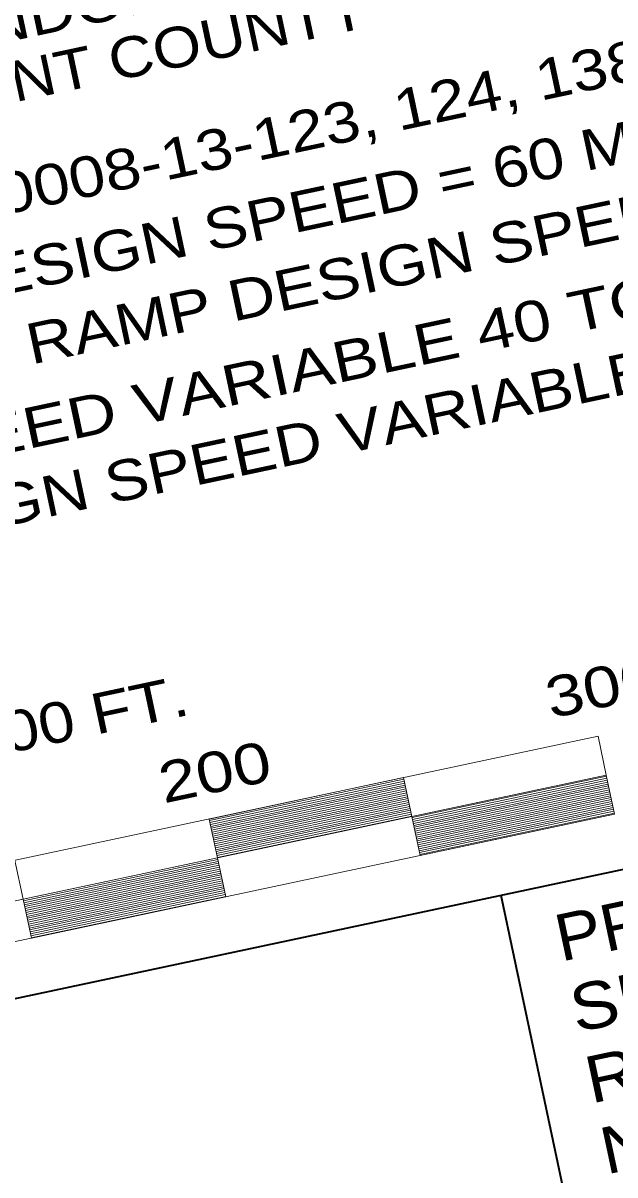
# Model space of a CAD drawing. Extents: x 2357218 to 2371708, y 6973728 to 6980157.
# Drawn here: x 2370806.3 to 2370955.3, y 6976807.8 to 6977097.4 of the extents above; entities that cross this region are included whole.
import ezdxf
from ezdxf.enums import TextEntityAlignment as Align

# ---------------------------------------------------------------- set-up
doc = ezdxf.new("R2010")
doc.units = 0
doc.header["$LTSCALE"] = 2
doc.layers.add('61', color=7, linetype='Continuous')
doc.layers.add('62', color=7, linetype='Continuous', lineweight=13)
doc.layers.add('63', color=7, linetype='Continuous', lineweight=13)

msp = doc.modelspace()

# ---------------------------------------------------------------- linework, layer by layer
at = {"layer": '62', "lineweight": 35}
for p, q in [((2371176.22, 6976931.098), (2370539.396, 6976795.736)), ((2370972.547, 6976661.874), (2370926.598, 6976878.04))]:
    msp.add_line(p, q, dxfattribs=at)
at = {"layer": '62'}
for p, q in [((2370559.68, 6976834.897), (2370950.993, 6976918.073)), ((2370950.993, 6976918.073), (2370953.073, 6976908.29)), ((2370561.761, 6976825.114), (2370953.073, 6976908.29)), ((2370853.246, 6976896.896), (2370902.159, 6976907.293)), ((2370853.351, 6976896.406), (2370902.264, 6976906.803)), ((2370902.078, 6976907.676), (2370904.157, 6976897.894)), ((2370904.214, 6976897.632), (2370953.127, 6976908.028)), ((2370904.318, 6976897.143), (2370953.231, 6976907.54)), ((2370904.421, 6976896.653), (2370953.336, 6976907.051)), ((2370904.524, 6976896.164), (2370953.439, 6976906.56)), ((2370953.073, 6976908.29), (2370955.152, 6976898.507)), ((2370853.455, 6976895.917), (2370902.367, 6976906.314)), ((2370853.557, 6976895.429), (2370902.472, 6976905.825)), ((2370853.661, 6976894.94), (2370902.575, 6976905.335)), ((2370853.765, 6976894.45), (2370902.679, 6976904.847)), ((2370853.87, 6976893.961), (2370902.784, 6976904.358)), ((2370853.973, 6976893.472), (2370902.887, 6976903.868)), ((2370904.628, 6976895.676), (2370953.543, 6976906.072)), ((2370904.732, 6976895.186), (2370953.647, 6976905.583)), ((2370904.836, 6976894.697), (2370953.751, 6976905.095)), ((2370904.94, 6976894.208), (2370953.856, 6976904.606)), ((2370905.045, 6976893.719), (2370953.959, 6976904.116)), ((2370905.149, 6976893.23), (2370954.063, 6976903.628)), ((2370854.077, 6976892.983), (2370902.991, 6976903.379)), ((2370854.182, 6976892.494), (2370903.095, 6976902.889)), ((2370854.285, 6976892.004), (2370903.2, 6976902.4)), ((2370854.39, 6976891.515), (2370903.304, 6976901.912)), ((2370854.493, 6976891.026), (2370903.407, 6976901.423)), ((2370854.598, 6976890.537), (2370903.51, 6976900.935)), ((2370905.253, 6976892.741), (2370954.168, 6976903.138)), ((2370905.357, 6976892.252), (2370954.272, 6976902.649)), ((2370905.459, 6976891.762), (2370954.376, 6976902.16)), ((2370905.564, 6976891.273), (2370954.479, 6976901.67)), ((2370905.668, 6976890.783), (2370954.583, 6976901.181)), ((2370905.772, 6976890.294), (2370954.687, 6976900.691)), ((2370854.701, 6976890.048), (2370903.615, 6976900.445)), ((2370854.805, 6976889.559), (2370903.72, 6976899.956)), ((2370854.91, 6976889.07), (2370903.823, 6976899.468)), ((2370855.013, 6976888.581), (2370903.927, 6976898.978)), ((2370855.118, 6976888.092), (2370904.031, 6976898.489)), ((2370855.222, 6976887.603), (2370904.134, 6976897.999)), ((2370904.157, 6976897.894), (2370906.237, 6976888.11)), ((2370905.876, 6976889.805), (2370954.791, 6976900.202)), ((2370905.98, 6976889.316), (2370954.896, 6976899.713)), ((2370906.085, 6976888.827), (2370954.999, 6976899.224)), ((2370906.189, 6976888.338), (2370955.104, 6976898.735)), ((2370853.165, 6976897.279), (2370855.245, 6976887.496)), ((2370804.251, 6976886.882), (2370806.329, 6976877.099)), ((2370806.41, 6976876.716), (2370855.324, 6976887.113)), ((2370806.515, 6976876.227), (2370855.429, 6976886.624)), ((2370855.245, 6976887.496), (2370857.323, 6976877.714)), ((2370806.618, 6976875.738), (2370855.533, 6976886.135)), ((2370806.722, 6976875.249), (2370855.638, 6976885.646)), ((2370806.827, 6976874.76), (2370855.741, 6976885.157)), ((2370806.93, 6976874.271), (2370855.844, 6976884.669)), ((2370807.034, 6976873.782), (2370855.949, 6976884.18)), ((2370807.138, 6976873.293), (2370856.052, 6976883.691)), ((2370807.242, 6976872.804), (2370856.157, 6976883.202)), ((2370807.347, 6976872.315), (2370856.261, 6976882.712)), ((2370807.45, 6976871.825), (2370856.364, 6976882.223)), ((2370807.555, 6976871.336), (2370856.469, 6976881.734)), ((2370807.658, 6976870.846), (2370856.572, 6976881.244)), ((2370807.763, 6976870.356), (2370856.678, 6976880.754)), ((2370807.866, 6976869.868), (2370856.781, 6976880.265)), ((2370807.97, 6976869.379), (2370856.884, 6976879.776)), ((2370808.074, 6976868.89), (2370856.988, 6976879.288)), ((2370808.178, 6976868.401), (2370857.092, 6976878.798)), ((2370808.283, 6976867.912), (2370857.197, 6976878.309)), ((2370808.387, 6976867.424), (2370857.3, 6976877.82)), ((2370806.329, 6976877.099), (2370808.409, 6976867.316))]:
    msp.add_line(p, q, dxfattribs=at)
for points in [[(2370855.245, 6976887.496), (2370904.157, 6976897.894), (2370902.078, 6976907.676), (2370853.165, 6976897.279)], [(2370906.237, 6976888.11), (2370955.152, 6976898.507), (2370953.073, 6976908.29), (2370904.157, 6976897.894)], [(2370757.416, 6976866.702), (2370806.329, 6976877.099), (2370804.251, 6976886.882), (2370755.336, 6976876.485)], [(2370808.409, 6976867.316), (2370857.323, 6976877.714), (2370855.245, 6976887.496), (2370806.329, 6976877.099)]]:
    msp.add_lwpolyline(points, close=True, dxfattribs=at)
at = {"layer": '63'}
for p, q in [((2370559.68, 6976834.897), (2370950.993, 6976918.073)), ((2370950.993, 6976918.073), (2370953.073, 6976908.29)), ((2370561.761, 6976825.114), (2370953.073, 6976908.29)), ((2370853.246, 6976896.896), (2370902.159, 6976907.293)), ((2370853.351, 6976896.406), (2370902.264, 6976906.803)), ((2370902.078, 6976907.676), (2370904.157, 6976897.894)), ((2370904.214, 6976897.632), (2370953.127, 6976908.028)), ((2370904.318, 6976897.143), (2370953.231, 6976907.54)), ((2370904.421, 6976896.653), (2370953.336, 6976907.051)), ((2370904.524, 6976896.164), (2370953.439, 6976906.56)), ((2370953.073, 6976908.29), (2370955.152, 6976898.507)), ((2370853.455, 6976895.917), (2370902.367, 6976906.314)), ((2370853.557, 6976895.429), (2370902.472, 6976905.825)), ((2370853.661, 6976894.94), (2370902.575, 6976905.335)), ((2370853.765, 6976894.45), (2370902.679, 6976904.847)), ((2370853.87, 6976893.961), (2370902.784, 6976904.358)), ((2370853.973, 6976893.472), (2370902.887, 6976903.868)), ((2370904.628, 6976895.676), (2370953.543, 6976906.072)), ((2370904.732, 6976895.186), (2370953.647, 6976905.583)), ((2370904.836, 6976894.697), (2370953.751, 6976905.095)), ((2370904.94, 6976894.208), (2370953.856, 6976904.606)), ((2370905.045, 6976893.719), (2370953.959, 6976904.116)), ((2370905.149, 6976893.23), (2370954.063, 6976903.628)), ((2370854.077, 6976892.983), (2370902.991, 6976903.379)), ((2370854.182, 6976892.494), (2370903.095, 6976902.889)), ((2370854.285, 6976892.004), (2370903.2, 6976902.4)), ((2370854.39, 6976891.515), (2370903.304, 6976901.912)), ((2370854.493, 6976891.026), (2370903.407, 6976901.423)), ((2370854.598, 6976890.537), (2370903.51, 6976900.935)), ((2370905.253, 6976892.741), (2370954.168, 6976903.138)), ((2370905.357, 6976892.252), (2370954.272, 6976902.649)), ((2370905.459, 6976891.762), (2370954.376, 6976902.16)), ((2370905.564, 6976891.273), (2370954.479, 6976901.67)), ((2370905.668, 6976890.783), (2370954.583, 6976901.181)), ((2370905.772, 6976890.294), (2370954.687, 6976900.691)), ((2370563.839, 6976815.332), (2370955.152, 6976898.507)), ((2370854.701, 6976890.048), (2370903.615, 6976900.445)), ((2370854.805, 6976889.559), (2370903.72, 6976899.956)), ((2370854.91, 6976889.07), (2370903.823, 6976899.468)), ((2370855.013, 6976888.581), (2370903.927, 6976898.978)), ((2370855.118, 6976888.092), (2370904.031, 6976898.489)), ((2370855.222, 6976887.603), (2370904.134, 6976897.999)), ((2370904.157, 6976897.894), (2370906.237, 6976888.11)), ((2370905.876, 6976889.805), (2370954.791, 6976900.202)), ((2370905.98, 6976889.316), (2370954.896, 6976899.713)), ((2370906.085, 6976888.827), (2370954.999, 6976899.224)), ((2370906.189, 6976888.338), (2370955.104, 6976898.735)), ((2370853.165, 6976897.279), (2370855.245, 6976887.496)), ((2370804.251, 6976886.882), (2370806.329, 6976877.099)), ((2370806.41, 6976876.716), (2370855.324, 6976887.113)), ((2370806.515, 6976876.227), (2370855.429, 6976886.624)), ((2370855.245, 6976887.496), (2370857.323, 6976877.714)), ((2370806.618, 6976875.738), (2370855.533, 6976886.135)), ((2370806.722, 6976875.249), (2370855.638, 6976885.646)), ((2370806.827, 6976874.76), (2370855.741, 6976885.157)), ((2370806.93, 6976874.271), (2370855.844, 6976884.669)), ((2370807.034, 6976873.782), (2370855.949, 6976884.18)), ((2370807.138, 6976873.293), (2370856.052, 6976883.691)), ((2370807.242, 6976872.804), (2370856.157, 6976883.202)), ((2370807.347, 6976872.315), (2370856.261, 6976882.712)), ((2370807.45, 6976871.825), (2370856.364, 6976882.223)), ((2370807.555, 6976871.336), (2370856.469, 6976881.734)), ((2370807.658, 6976870.846), (2370856.572, 6976881.244)), ((2370807.763, 6976870.356), (2370856.678, 6976880.754)), ((2370807.866, 6976869.868), (2370856.781, 6976880.265)), ((2370807.97, 6976869.379), (2370856.884, 6976879.776)), ((2370808.074, 6976868.89), (2370856.988, 6976879.288)), ((2370808.178, 6976868.401), (2370857.092, 6976878.798)), ((2370808.283, 6976867.912), (2370857.197, 6976878.309)), ((2370808.387, 6976867.424), (2370857.3, 6976877.82)), ((2370806.329, 6976877.099), (2370808.409, 6976867.316))]:
    msp.add_line(p, q, dxfattribs=at)
for points in [[(2370855.245, 6976887.496), (2370904.157, 6976897.894), (2370902.078, 6976907.676), (2370853.165, 6976897.279)], [(2370906.237, 6976888.11), (2370955.152, 6976898.507), (2370953.073, 6976908.29), (2370904.157, 6976897.894)], [(2370757.416, 6976866.702), (2370806.329, 6976877.099), (2370804.251, 6976886.882), (2370755.336, 6976876.485)], [(2370808.409, 6976867.316), (2370857.323, 6976877.714), (2370855.245, 6976887.496), (2370806.329, 6976877.099)]]:
    msp.add_lwpolyline(points, close=True, dxfattribs=at)

# ---------------------------------------------------------------- texts
at = {"layer": '61'}
for s, width, p in [('LIMITS: IH820 NORTH INTERCHANGE AT SH121', 1.15, (2370806.917, 6977109.14)), ('SOUTH TO RANDOL MILL ROAD', 1.2, (2370810.078, 6977094.271)), ('IN TARRANT COUNTY', 1.15, (2370813.239, 6977079.404))]:
    msp.add_text(s, height=10.2, rotation=12, dxfattribs=dict(at, width=width)).set_placement(p, align=Align.CENTER)
at = {"layer": '62'}
for s, height, width, p in [('CONTROL NO.  0008-13-123, 124, 138', 10.2, 1.2, (2370681.072, 6977023.559)), ('PRELIMINARY PLAN', 11.74, 1.1, (2370941.659, 6976861.386)), ('SUBMITTAL FOR', 11.74, 1.15, (2370945.453, 6976843.542)), ('NOT FOR CONSTRUCTION.', 11.74, 1.15, (2370953.039, 6976807.854)), ('REVIEW ONLY', 11.74, 1.15, (2370949.246, 6976825.698))]:
    msp.add_text(s, height=height, rotation=12, dxfattribs=dict(at, width=width)).set_placement(p)
for s, width, p in [('MAIN LANES DESIGN SPEED = 60 MPH', 1.2, (2370834.598, 6977036.084)), ('DIRECT CONNECTOR & RAMP DESIGN SPEED = 50 MPH', 1.2, (2370838.46, 6977017.911)), ('RAMP DESIGN SPEED VARIABLE 40 TO 50 MPH', 1.25, (2370842.737, 6976997.784)), ('FRONTAGE ROAD DESIGN SPEED VARIABLE 35 TO 40 MPH', 1.2, (2370847.295, 6976980.56)), ('300', 1.25, (2370952.994, 6976925.492)), ('SCALE:  1 INCH = 100 FT.', 1.2, (2370752.789, 6976903.182)), ('200', 1.25, (2370855.618, 6976904.13))]:
    msp.add_text(s, height=10.2, rotation=12, dxfattribs=dict(at, width=width)).set_placement(p, align=Align.CENTER)
at = {"layer": '63'}
for s, width, p in [('MAIN LANES DESIGN SPEED = 60 MPH', 1.2, (2370834.598, 6977036.084)), ('DIRECT CONNECTOR & RAMP DESIGN SPEED = 50 MPH', 1.2, (2370838.46, 6977017.911)), ('300', 1.25, (2370952.994, 6976925.492)), ('200', 1.25, (2370855.618, 6976904.13))]:
    msp.add_text(s, height=10.2, rotation=12, dxfattribs=dict(at, width=width)).set_placement(p, align=Align.CENTER)

doc.saveas('drawing.dxf')
